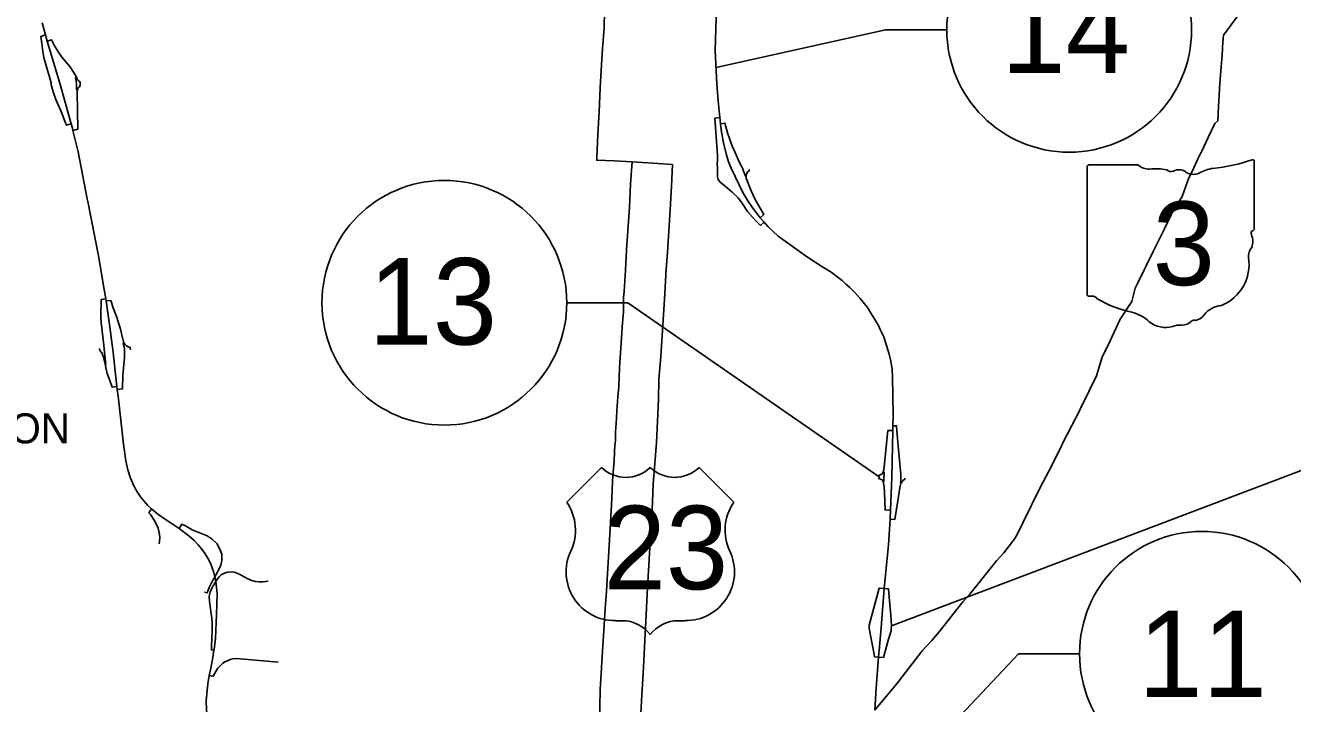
# Model space of a CAD drawing. Extents: x -1146 to -445, y -1283 to -822.
# Drawn here: x -909.3 to -856.5, y -1032.2 to -1003.9 of the extents above; entities that cross this region are included whole.
import ezdxf

# ---------------------------------------------------------------- set-up
doc = ezdxf.new("R2010")
doc.units = 0
for name, color, linetype in [('Default', 7, 'Continuous'), ('GM_X_Corporation_Text', 7, 'Continuous'), ('GM_X_Interchange_Ramps', 7, 'Continuous'), ('GM_X_Interstate_Route', 7, 'Continuous'), ('GM_X_State_Route', 7, 'Continuous'), ('GM_X_State_Shield', 7, 'Continuous'), ('GM_X_US_Route', 7, 'Continuous'), ('GM_X_US_Shield', 7, 'Continuous')]:
    doc.layers.add(name, color=color, linetype=linetype)

msp = doc.modelspace()

# ---------------------------------------------------------------- linework, layer by layer
at = {"layer": 'Default'}
for points in [[(-870.898, -1004.109), (-873.445, -1004.109), (-880.505, -1005.68)], [(-886.717, -1015.472), (-884.17, -1015.472), (-873.721, -1022.725)], [(-853.091, -1022.261), (-855.638, -1022.261), (-873.197, -1028.924)], [(-865.374, -1030.089), (-867.921, -1030.089), (-873.382, -1035.9)]]:
    msp.add_lwpolyline(points, dxfattribs=at)
for centre in [(-865.804, -1004.109), (-891.812, -1015.472), (-860.28, -1030.089)]:
    msp.add_circle(centre, 5.094, dxfattribs=at)
at = {"layer": 'GM_X_Interchange_Ramps'}
for points in [[(-908.412, -1004.323), (-908.606, -1004.384), (-908.566, -1004.681), (-908.52, -1005.013), (-908.476, -1005.258), (-908.348, -1005.748), (-908.216, -1006.17), (-908.181, -1006.323)], [(-906.975, -1006.369), (-906.97, -1006.271), (-907.019, -1006.251), (-907.063, -1006.202), (-907.088, -1006.16), (-907.114, -1006.105), (-907.178, -1005.983), (-907.279, -1005.825), (-907.404, -1005.632), (-907.73, -1005.247), (-907.902, -1004.992), (-908.049, -1004.746), (-908.162, -1004.52), (-908.343, -1004.577)], [(-908.181, -1006.323), (-908.174, -1006.405), (-908.096, -1006.695), (-907.979, -1007.011), (-907.762, -1007.507), (-907.606, -1007.911), (-907.545, -1008.075), (-907.338, -1008.025)], [(-907.272, -1008.297), (-907.071, -1008.249), (-907.092, -1006.704), (-907.08, -1006.612), (-907.067, -1006.546), (-907.028, -1006.499), (-906.983, -1006.471), (-906.975, -1006.369)], [(-907.117, -1006.364), (-907.132, -1006.242), (-907.161, -1006.105), (-907.114, -1006.105)], [(-907.08, -1006.612), (-907.122, -1006.613), (-907.124, -1006.478), (-907.117, -1006.364)], [(-880.35, -1007.755), (-880.548, -1007.784), (-880.448, -1009.33), (-880.45, -1009.502), (-880.452, -1009.717), (-880.45, -1009.833)], [(-879.385, -1009.897), (-879.443, -1009.783), (-879.551, -1009.571), (-879.666, -1009.315), (-879.723, -1009.189), (-879.821, -1008.975), (-879.934, -1008.676), (-880.026, -1008.403), (-880.142, -1007.995), (-880.32, -1008.021)], [(-880.45, -1009.833), (-880.448, -1009.929), (-880.444, -1010.229), (-880.413, -1010.343), (-880.348, -1010.444), (-880.131, -1010.624), (-879.827, -1010.867), (-879.58, -1011.101), (-879.428, -1011.314), (-879.188, -1011.669), (-878.982, -1011.911), (-878.837, -1012.077), (-878.647, -1012.255), (-878.501, -1012.122)], [(-879.252, -1010.198), (-879.278, -1010.208), (-879.357, -1009.999), (-879.385, -1009.897)], [(-878.663, -1011.937), (-878.508, -1011.797), (-878.869, -1011.175), (-879.04, -1010.809), (-879.245, -1010.283), (-879.252, -1010.198), (-879.231, -1010.099), (-879.189, -1010.032), (-879.131, -1009.987), (-879.128, -1009.918)], [(-905.904, -1015.306), (-906.098, -1015.343), (-906.106, -1016.032), (-906.097, -1016.288), (-905.988, -1017.242), (-905.977, -1017.389)], [(-904.879, -1017.438), (-904.883, -1017.337), (-904.971, -1017.313), (-905.045, -1017.265), (-905.112, -1017.195), (-905.147, -1017.138), (-905.182, -1017.041), (-905.211, -1016.936), (-905.295, -1016.575), (-905.458, -1016.04), (-905.579, -1015.72), (-905.695, -1015.372), (-905.89, -1015.397)], [(-906.166, -1017.379), (-906.153, -1017.463), (-906.088, -1017.537), (-906.056, -1017.592), (-906.02, -1017.668), (-905.998, -1017.732), (-905.932, -1018.032), (-905.893, -1018.235), (-905.842, -1018.411), (-905.733, -1018.714), (-905.64, -1018.985), (-905.439, -1018.963)], [(-905.977, -1017.389), (-905.959, -1017.523), (-905.899, -1018.026), (-905.932, -1018.032)], [(-905.425, -1019.085), (-905.208, -1019.06), (-905.195, -1018.493), (-905.123, -1017.755), (-905.128, -1017.539), (-905.125, -1017.435)], [(-905.125, -1017.435), (-905.129, -1017.37), (-905.177, -1017.157), (-905.147, -1017.138)], [(-872.809, -1022.746), (-872.808, -1022.624), (-872.917, -1021.427), (-872.973, -1020.811), (-872.988, -1020.594), (-873.142, -1020.595)], [(-873.146, -1020.795), (-873.359, -1020.797), (-873.445, -1021.746), (-873.512, -1022.322), (-873.524, -1022.432), (-873.546, -1022.527), (-873.593, -1022.59), (-873.65, -1022.623), (-873.716, -1022.649), (-873.721, -1022.725)], [(-873.721, -1022.725), (-873.725, -1022.803), (-873.656, -1022.815), (-873.625, -1022.825), (-873.592, -1022.842), (-873.573, -1022.86), (-873.553, -1022.903), (-873.533, -1022.999), (-873.512, -1023.127), (-873.494, -1023.392), (-873.465, -1024.099), (-873.243, -1024.11)], [(-873.515, -1022.727), (-873.515, -1022.816), (-873.514, -1022.902), (-873.553, -1022.903)], [(-873.546, -1022.527), (-873.512, -1022.53), (-873.513, -1022.635), (-873.515, -1022.727)], [(-872.79, -1022.975), (-872.824, -1022.972), (-872.816, -1022.864), (-872.809, -1022.746)], [(-873.259, -1024.481), (-873.058, -1024.492), (-872.948, -1023.804), (-872.843, -1023.1), (-872.83, -1023.054), (-872.808, -1023.002), (-872.79, -1022.975), (-872.762, -1022.915), (-872.736, -1022.884), (-872.714, -1022.862), (-872.686, -1022.844), (-872.651, -1022.827), (-872.648, -1022.775)], [(-904.005, -1024.048), (-904.11, -1024.212), (-904.045, -1024.292), (-903.86, -1024.562), (-903.726, -1024.858), (-903.67, -1025.109), (-903.659, -1025.26), (-903.674, -1025.401), (-903.681, -1025.506)], [(-901.798, -1027.528), (-901.684, -1027.543), (-901.605, -1027.33), (-901.499, -1027.129), (-901.361, -1026.88), (-901.236, -1026.655), (-901.12, -1026.404), (-901.079, -1026.204), (-901.079, -1025.943), (-901.15, -1025.725), (-901.282, -1025.5), (-901.478, -1025.322), (-901.688, -1025.183), (-902.303, -1024.932), (-902.584, -1024.762), (-902.736, -1024.686), (-902.856, -1024.873)], [(-899.142, -1027.058), (-899.371, -1027.098), (-899.527, -1027.098), (-899.69, -1027.074), (-899.83, -1027.033), (-900.023, -1026.946), (-900.266, -1026.819), (-900.411, -1026.749), (-900.563, -1026.695), (-900.728, -1026.674), (-900.831, -1026.687), (-900.959, -1026.724), (-901.095, -1026.798), (-901.177, -1026.872), (-901.255, -1026.967), (-901.328, -1027.082), (-901.482, -1027.321), (-901.564, -1027.523), (-901.601, -1027.692), (-901.593, -1027.915), (-901.54, -1028.195), (-901.511, -1028.422), (-901.486, -1028.607), (-901.478, -1028.817), (-901.478, -1029.105), (-901.49, -1029.46), (-901.507, -1029.744), (-901.507, -1029.929), (-901.402, -1029.942)], [(-873.505, -1027.371), (-873.721, -1027.355), (-874.127, -1028.899), (-874.129, -1028.978)], [(-873.21, -1029.035), (-873.197, -1028.926), (-873.233, -1028.484), (-873.301, -1027.723), (-873.322, -1027.385), (-873.505, -1027.371)], [(-874.129, -1028.978), (-874.13, -1029.041), (-873.939, -1030.03), (-873.915, -1030.209), (-873.741, -1030.221)], [(-873.741, -1030.221), (-873.535, -1030.236), (-873.325, -1029.473), (-873.222, -1029.137), (-873.21, -1029.035)], [(-901.595, -1030.996), (-901.432, -1031.021), (-901.325, -1030.828), (-901.239, -1030.688), (-901.156, -1030.597), (-901.045, -1030.494), (-900.946, -1030.424), (-900.839, -1030.375), (-900.728, -1030.329), (-900.724, -1030.329), (-900.617, -1030.304), (-900.497, -1030.288), (-900.312, -1030.296), (-898.725, -1030.432)]]:
    msp.add_lwpolyline(points, dxfattribs=at)
at = {"layer": 'GM_X_Interstate_Route'}
for points in [[(-879.879, -1009.865), (-879.984, -1009.605), (-880.067, -1009.321), (-880.181, -1008.881), (-880.277, -1008.369), (-880.32, -1008.021), (-880.35, -1007.755), (-880.418, -1007.065), (-880.473, -1006.36), (-880.538, -1004.983), (-880.495, -1003.622), (-880.485, -1003.491), (-880.468, -1002.89), (-880.436, -1002.425), (-880.299, -1001.442)], [(-873.19, -1022.731), (-873.146, -1020.795), (-873.142, -1020.595), (-873.133, -1020.167), (-873.151, -1019.324), (-873.16, -1018.586), (-873.176, -1018.258), (-873.231, -1017.908), (-873.314, -1017.557), (-873.417, -1017.214), (-873.527, -1016.897), (-873.671, -1016.588), (-873.747, -1016.423), (-873.898, -1016.169), (-874.07, -1015.873), (-874.207, -1015.667), (-874.502, -1015.289), (-874.722, -1015.041), (-874.942, -1014.835), (-875.103, -1014.692), (-875.259, -1014.54), (-875.708, -1014.203), (-876.101, -1013.957), (-876.7, -1013.57), (-877.915, -1012.696), (-878.349, -1012.295), (-878.501, -1012.122), (-878.663, -1011.937), (-878.833, -1011.72), (-878.973, -1011.532), (-879.186, -1011.236), (-879.395, -1010.876), (-879.546, -1010.564), (-879.879, -1009.865)], [(-873.634, -1028.998), (-873.505, -1027.371), (-873.323, -1025.549), (-873.259, -1024.481), (-873.243, -1024.11), (-873.19, -1022.731)], [(-873.717, -1029.949), (-873.634, -1028.998)], [(-873.899, -1032.438), (-873.899, -1032.438), (-873.835, -1031.508), (-873.741, -1030.221), (-873.717, -1029.949)]]:
    msp.add_lwpolyline(points, dxfattribs=at)
at = {"layer": 'GM_X_State_Route'}
for points in [[(-859.422, -1004.861), (-859.421, -1004.844), (-859.407, -1004.65), (-859.393, -1004.464), (-859.383, -1004.328), (-858.751, -1003.47), (-858.724, -1003.426), (-858.321, -1002.852), (-857.837, -1002.03), (-857.36, -1001.235), (-857.069, -1000.758)], [(-907.821, -1006.328), (-908.343, -1004.577), (-908.412, -1004.323), (-908.549, -1003.819)], [(-860.314, -1009.214), (-860.285, -1009.155), (-860.016, -1008.595), (-859.737, -1008.016), (-859.621, -1007.901), (-859.59, -1007.301), (-859.553, -1006.593), (-859.548, -1006.529), (-859.521, -1006.174), (-859.482, -1005.648), (-859.445, -1005.162), (-859.423, -1004.871), (-859.422, -1004.861)], [(-907.294, -1008.206), (-907.338, -1008.025), (-907.821, -1006.328)], [(-906.672, -1011.144), (-907.053, -1009.194), (-907.272, -1008.297), (-907.294, -1008.206)], [(-867.014, -1023.16), (-866.548, -1022.279), (-866.123, -1021.426), (-866.081, -1021.335), (-865.698, -1020.582), (-865.373, -1019.971), (-865.336, -1019.857), (-865.03, -1019.259), (-864.977, -1019.136), (-864.674, -1018.512), (-864.439, -1017.732), (-864.091, -1017.024), (-864.03, -1016.901), (-863.68, -1016.16), (-863.193, -1015.421), (-863.062, -1014.868), (-862.953, -1014.647), (-862.682, -1014.095), (-862.603, -1013.934), (-862.308, -1013.339), (-862.211, -1013.143), (-861.858, -1012.429), (-861.574, -1011.836), (-861.527, -1011.737), (-861.107, -1011.05), (-860.82, -1010.266), (-860.693, -1010.002), (-860.431, -1009.457), (-860.338, -1009.265), (-860.314, -1009.214)], [(-905.971, -1014.915), (-906.212, -1013.518), (-906.65, -1011.256), (-906.672, -1011.144)], [(-905.675, -1016.916), (-905.694, -1016.783), (-905.89, -1015.397), (-905.904, -1015.306), (-905.971, -1014.915)], [(-905.395, -1019.355), (-905.425, -1019.085), (-905.439, -1018.963), (-905.605, -1017.422), (-905.675, -1016.916)], [(-904.005, -1024.048), (-904.149, -1023.919), (-904.317, -1023.725), (-904.459, -1023.557), (-904.601, -1023.351), (-904.725, -1023.128), (-904.872, -1022.773), (-904.982, -1022.424), (-905.071, -1022.056), (-905.171, -1021.363), (-905.395, -1019.355)], [(-873, -1031.352), (-872.901, -1031.232), (-871.929, -1029.958), (-871.523, -1029.538), (-871.221, -1029.167), (-870.235, -1027.929), (-869.935, -1027.602), (-869.557, -1027.114), (-868.825, -1026.222), (-868.52, -1025.882), (-868.145, -1025.398), (-868.064, -1025.285), (-868.01, -1025.191), (-867.79, -1024.758), (-867.718, -1024.609), (-867.396, -1023.958), (-867.351, -1023.847), (-867.014, -1023.16)], [(-901.657, -1031.354), (-901.656, -1031.343), (-901.595, -1030.996), (-901.541, -1030.75), (-901.458, -1030.33), (-901.402, -1029.942), (-901.397, -1029.915), (-901.341, -1029.432), (-901.296, -1028.462), (-901.27, -1027.582), (-901.313, -1027.199), (-901.328, -1027.082), (-901.338, -1027.012), (-901.361, -1026.88), (-901.409, -1026.709), (-901.474, -1026.508), (-901.55, -1026.316), (-901.646, -1026.129), (-901.762, -1025.927), (-901.908, -1025.731), (-902.054, -1025.549), (-902.231, -1025.372), (-902.446, -1025.172), (-902.856, -1024.873), (-903.139, -1024.676), (-903.416, -1024.49), (-903.734, -1024.268), (-904.005, -1024.048)], [(-900.179, -1035.753), (-900.328, -1035.514), (-900.659, -1034.979), (-901.05, -1034.385), (-901.318, -1033.903), (-901.441, -1033.618), (-901.558, -1033.24), (-901.643, -1032.918), (-901.678, -1032.73), (-901.711, -1032.405), (-901.721, -1032.039), (-901.703, -1031.759), (-901.684, -1031.595), (-901.657, -1031.354)], [(-873.899, -1032.438), (-873.71, -1032.21), (-873, -1031.352)]]:
    msp.add_lwpolyline(points, dxfattribs=at)
at = {"layer": 'GM_X_State_Shield'}
for p, q in [((-865.061, -1009.828), (-865.061, -1015.112)), ((-862.954, -1009.737), (-864.992, -1009.737)), ((-858.1, -1012.37), (-858.1, -1009.607)), ((-858.101, -1012.37), (-858.1, -1012.37))]:
    msp.add_line(p, q, dxfattribs=at)
for centre, radius, start, end in [((-860.579, -1002.535), 7.382, 275.8445, 288.9065), ((-858.177, -1009.595), 0.0775, 351.8621, 97.738), ((-864.981, -1009.817), 0.0806, 98.1301, 188.1301), ((-862.468, -1009.124), 0.782, 231.6195, 271.1119), ((-862.209, -1012.703), 2.808, 80.4867, 94.9883), ((-861.571, -1009.79), 0.226, 219.7921, 297.1024), ((-861.24, -1010.4), 0.469, 54.4667, 119.1411), ((-860.635, -1009.563), 0.564, 233.8562, 294.8282), ((-859.638, -1011.351), 1.485, 97.3462, 120.7689), ((-858.118, -1012.573), 0.12, 107.944, 210.337), ((-858.881, -1012.922), 0.72, 340.033, 23.6496), ((-858.182, -1012.381), 0.0829, 289.6038, 7.7341), ((-857.822, -1013.527), 0.524, 136.8065, 186.9296), ((-860.166, -1013.878), 1.846, 292.3089, 8.9858), ((-864.98, -1015.123), 0.0814, 171.9584, 258.3066), ((-864.968, -1014.583), 0.621, 267.339, 280.6039), ((-864.841, -1015.416), 0.224, 29.7484, 93.2717), ((-862.014, -1010.67), 5.331, 240.4129, 257.1985), ((-863.604, -1017.485), 1.668, 47.1842, 75.836), ((-859.387, -1016.595), 1.011, 94.4031, 142.5768), ((-861.8, -1015.443), 1.058, 230.7004, 286.2918), ((-861.188, -1017.269), 0.87, 85.6951, 111.2099), ((-861.111, -1015.838), 0.564, 268.777, 315.5493), ((-860.601, -1016.35), 0.159, 65.7517, 132.6484), ((-860.669, -1015.624), 0.597, 282.8732, 323.2771)]:
    msp.add_arc(centre, radius, start, end, dxfattribs=at)
at = {"layer": 'GM_X_US_Route'}
for points in [[(-885.259, -1005.328), (-885.234, -1004.896), (-885.156, -1004.04), (-885.15, -1003.32), (-885.098, -1002.6), (-885.063, -1002.025), (-885.014, -1001.146), (-884.956, -1000.532), (-884.903, -999.705), (-884.888, -999.47), (-884.85, -998.876), (-884.788, -997.901), (-884.748, -997.271), (-884.702, -996.553), (-884.677, -996.149), (-884.634, -995.472), (-884.605, -994.976), (-884.511, -993.471)], [(-883.989, -1009.604), (-884.744, -1009.558), (-885.471, -1009.537), (-885.472, -1009.42), (-885.424, -1008.467), (-885.367, -1007.53), (-885.325, -1006.505), (-885.259, -1005.328)], [(-883.989, -1009.604), (-884.065, -1010.522), (-884.108, -1011.494), (-884.232, -1013.271), (-884.272, -1014.116), (-884.327, -1015.005), (-884.351, -1015.254), (-884.362, -1015.854), (-884.418, -1016.481), (-884.429, -1016.719), (-884.523, -1018.18), (-884.556, -1018.962), (-884.589, -1019.392), (-884.639, -1019.972), (-884.647, -1020.271), (-884.684, -1020.857), (-884.695, -1021.161), (-884.709, -1021.363)], [(-882.316, -1009.712), (-883.137, -1009.66), (-883.989, -1009.604)], [(-882.595, -1014.311), (-882.591, -1014.248), (-882.53, -1013.381), (-882.471, -1012.488), (-882.415, -1011.601), (-882.356, -1010.615), (-882.316, -1009.712)], [(-883.046, -1022.164), (-882.989, -1021.284), (-882.941, -1020.405), (-882.9, -1019.502), (-882.889, -1018.656), (-882.803, -1017.707), (-882.778, -1017.261), (-882.746, -1016.836), (-882.686, -1015.974), (-882.64, -1015.105), (-882.595, -1014.311)], [(-884.709, -1021.363), (-884.71, -1021.378), (-884.746, -1022.055), (-884.798, -1022.689), (-884.807, -1022.914), (-884.835, -1023.619), (-884.892, -1024.636), (-884.947, -1025.579), (-885.005, -1026.516), (-885.062, -1027.482), (-885.129, -1028.408), (-885.131, -1028.442)], [(-883.376, -1027.595), (-883.311, -1026.629), (-883.256, -1025.682), (-883.193, -1024.758), (-883.142, -1023.743), (-883.127, -1023.037), (-883.127, -1023.021), (-883.046, -1022.164)], [(-883.635, -1032.58), (-883.596, -1031.796), (-883.536, -1030.918), (-883.462, -1029.515), (-883.408, -1028.461), (-883.376, -1027.595)], [(-885.131, -1028.442), (-885.199, -1029.554), (-885.267, -1030.651), (-885.283, -1030.92), (-885.324, -1031.576), (-885.334, -1032.296), (-885.338, -1032.46), (-885.394, -1033.311), (-885.512, -1035.228), (-885.508, -1035.455), (-885.464, -1035.758), (-885.372, -1036.345), (-885.288, -1037.29), (-885.114, -1038.187), (-885.076, -1038.701), (-884.978, -1039.349), (-884.711, -1040.907), (-884.539, -1042.252), (-884.391, -1043.114), (-884.34, -1043.511)]]:
    msp.add_lwpolyline(points, dxfattribs=at)
at = {"layer": 'GM_X_US_Shield'}
for p, q in [((-885.271, -1022.328), (-886.721, -1023.778)), ((-879.76, -1023.778), (-881.21, -1022.328)), ((-884.691, -1028.709), (-884.401, -1028.709)), ((-882.081, -1028.709), (-881.791, -1028.709))]:
    msp.add_line(p, q, dxfattribs=at)
for centre, radius, start, end in [((-884.256, -1021.292), 1.45, 225.573, 314.427), ((-882.226, -1021.292), 1.45, 225.573, 314.427), ((-888.384, -1024.942), 2.03, 334.5471, 35.0009), ((-878.097, -1024.942), 2.03, 144.9991, 205.4529), ((-884.714, -1026.678), 2.03, 154.8319, 270.6383), ((-881.768, -1026.678), 2.03, 269.3617, 25.1681), ((-884.401, -1030.159), 1.45, 36.8699, 90), ((-882.081, -1030.159), 1.45, 90, 143.1301)]:
    msp.add_arc(centre, radius, start, end, dxfattribs=at)

# ---------------------------------------------------------------- texts
at = {"layer": 'Default'}
for s, p in [('14', (-868.63, -1005.909)), ('13', (-894.971, -1017.214)), ('11', (-862.932, -1031.889))]:
    msp.add_text(s, height=3.6, dxfattribs=at).set_placement(p)
at = {"layer": 'GM_X_Corporation_Text'}
msp.add_text('ARLINGTON', height=1.25, rotation=0, dxfattribs=at).set_placement((-917.151, -1021.327))
at = {"layer": 'GM_X_State_Shield'}
msp.add_text('3', height=3.48, dxfattribs=at).set_placement((-862.331, -1014.739))
at = {"layer": 'GM_X_US_Shield'}
msp.add_text('23', height=3.4805, dxfattribs=at).set_placement((-885.178, -1027.403))

doc.saveas('drawing.dxf')
